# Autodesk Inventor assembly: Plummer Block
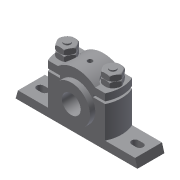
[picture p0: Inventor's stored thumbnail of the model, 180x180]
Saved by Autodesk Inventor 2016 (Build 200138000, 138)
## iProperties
Created: 2011-07
Part Number: Plummer Block
Document SubType Name: Assembly
Designer: CadCim
Author: CadCim
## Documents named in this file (7)
- C:\Autodesk Inventor 2016\c13\tut_01\Plummer Block\Plummer Block.iam
- C:\Autodesk Inventor 2016\c13\tut_01\Plummer Block\Casting.ipt
- C:\Autodesk Inventor 2016\c13\tut_01\Plummer Block\Brasses.ipt
- C:\Autodesk Inventor 2016\c13\tut_01\Plummer Block\Cap.ipt
- C:\Autodesk Inventor 2016\c13\tut_01\Plummer Block\Bolt.ipt
- C:\Autodesk Inventor 2016\c13\tut_01\Plummer Block\Nut.ipt
- C:\Autodesk Inventor 2016\c13\tut_01\Plummer Block\Lock Nut.ipt
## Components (9 placed, 6 different names)
1. Casting:1 — Mate:1, Mate:2, Insert:1, Insert:2, Angle:1, Angle:2
2. Brasses:1 — Mate:1, Mate:2, Mate:3, Mate:4
3. Cap:1 — Mate:3, Mate:4, Insert:3, Insert:4
4. Bolt:1 — Insert:1, Angle:1
5. Bolt:2 — Insert:2, Angle:2
6. Nut:1 — Insert:3, Insert:6
7. Nut:2 — Insert:4, Insert:5
8. Lock Nut:1 — Insert:6
9. Lock Nut:2 — Insert:5
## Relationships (12: Insert 6, Mate 4, Angle 2)
- Mate:1: Casting:1 ↔ Brasses:1
- Mate:2: Casting:1 ↔ Brasses:1
- Mate:3: Brasses:1 ↔ Cap:1
- Mate:4: Brasses:1 ↔ Cap:1
- Insert:1: Casting:1 ↔ Bolt:1
- Insert:2: Casting:1 ↔ Bolt:2
- Angle:1: Casting:1 ↔ Bolt:1
- Angle:2: Casting:1 ↔ Bolt:2
- Insert:3: Cap:1 ↔ Nut:1
- Insert:4: Cap:1 ↔ Nut:2
- Insert:5: Nut:2 ↔ Lock Nut:2
- Insert:6: Nut:1 ↔ Lock Nut:1
